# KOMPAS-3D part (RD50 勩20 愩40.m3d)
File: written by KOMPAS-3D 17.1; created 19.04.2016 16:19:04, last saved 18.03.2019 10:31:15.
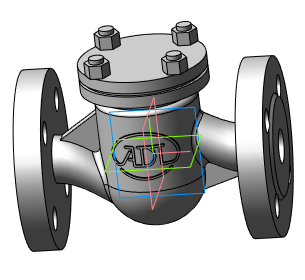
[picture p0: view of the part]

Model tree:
1. Операция без истории:2  (labels: Сталь 20  ГОСТ 1050-88)

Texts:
  RD50 Ду15 Ру40
  RD50 Ду20 Ру40
  RD50 Ду25 Ру40
  RD50 Ду32 Ру40
  RD50 Ду40 Ру40
  RD50 Ду50 Ру40
  RD50 Ду65 Ру40
  RD50 Ду80 Ру40
  RD50 Ду100 Ру40
  RD50 Ду125 Ру40
  RD50 Ду150 Ру40
  RD50 Ду200 Ру40
  RD50 Ду250 Ру40
  RD50 Ду300 Ру40
  RD50 Ду350 Ру40
  RD50 Ду400 Ру40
